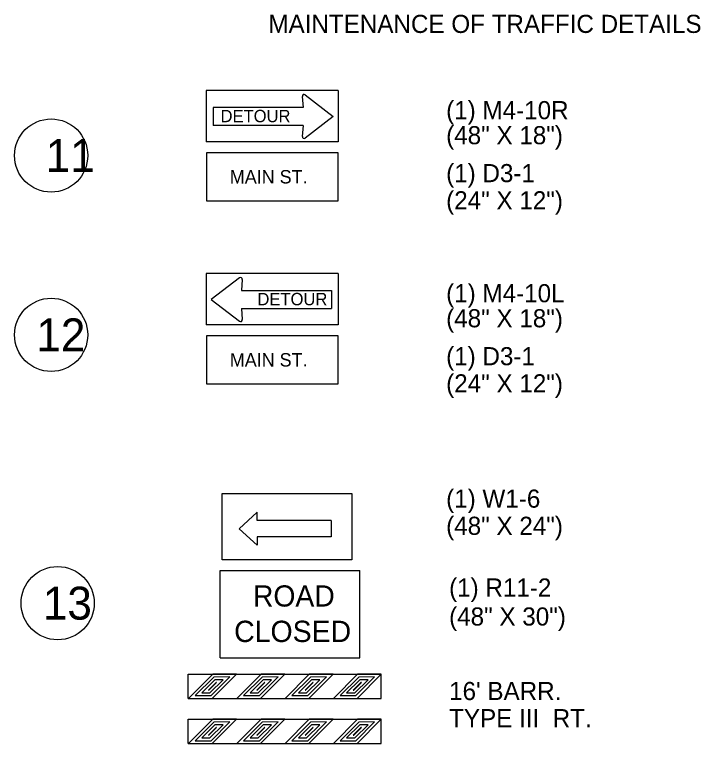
# Model space of a CAD drawing. Extents: x 988392 to 996681, y 1838707 to 1844440.
# Drawn here: x 995431 to 996681, y 1842900 to 1844227 of the extents above; entities that cross this region are included whole.
import ezdxf

# ---------------------------------------------------------------- set-up
doc = ezdxf.new("R2010")
doc.units = 0
for name, color, linetype in [('1', 7, 'Continuous'), ('3', 7, 'Continuous'), ('8', 7, 'Continuous'), ('G-ANNO-TEXT', 7, 'Continuous'), ('Level 8', 7, 'Continuous')]:
    doc.layers.add(name, color=color, linetype=linetype)

msp = doc.modelspace()

# ---------------------------------------------------------------- linework, layer by layer
at = {"layer": '1'}
for p, q in [((996020.9, 1844088.9), (995780.4, 1844088.9)), ((995780.4, 1844088.9), (995780.4, 1843995.4)), ((996020.9, 1844088.9), (996020.9, 1843995.4)), ((995955.4, 1844078), (995957, 1844057.9)), ((995960.7, 1844080.9), (996011.9, 1844041.4)), ((995957, 1844057.9), (995793, 1844057.9)), ((995793, 1844057.9), (995793, 1844024.9)), ((996011.9, 1844041.4), (995960.7, 1844001.9)), ((995957, 1844024.9), (995793, 1844024.9)), ((995957, 1844024.9), (995955.4, 1844004.8)), ((996020.9, 1843995.4), (995780.4, 1843995.4)), ((996020.9, 1843755.4), (995780.4, 1843755.4)), ((995780.4, 1843755.4), (995780.4, 1843662)), ((996020.9, 1843755.4), (996020.9, 1843662)), ((995840.7, 1843747.4), (995789.4, 1843708)), ((995845.9, 1843744.6), (995844.3, 1843724.5)), ((995844.3, 1843724.5), (996008.4, 1843724.5)), ((996008.4, 1843724.5), (996008.4, 1843691.5)), ((995789.4, 1843708), (995840.6, 1843668.5)), ((995844.3, 1843691.5), (996008.4, 1843691.5)), ((995844.3, 1843691.5), (995845.9, 1843671.4)), ((996020.9, 1843662), (995780.4, 1843662))]:
    msp.add_line(p, q, dxfattribs=at)
at = {"layer": '3'}
for p, q in [((995805.4, 1843055.5), (995805.4, 1843214.7)), ((995805.4, 1843214.7), (996060.3, 1843214.7)), ((996060.3, 1843055.5), (996060.3, 1843214.7)), ((995805.4, 1843055.5), (996060.3, 1843055.5)), ((995747.2, 1843025.6), (996099.3, 1843025.6)), ((995747.2, 1842981.4), (995747.2, 1843025.6)), ((996099.3, 1842981.4), (996099.3, 1843025.6)), ((995747.2, 1842981.4), (996099.3, 1842981.4)), ((996099.1, 1842981.5), (996099.3, 1842981.8)), ((995747.2, 1842943.6), (996099.3, 1842943.6)), ((995747.2, 1842899.5), (995747.2, 1842943.6)), ((996099.3, 1842899.5), (996099.3, 1842943.6)), ((996099.3, 1842899.5), (996099.3, 1842943.6)), ((995747.2, 1842899.5), (996099.3, 1842899.5))]:
    msp.add_line(p, q, dxfattribs=at)
for points in [[(995835.3, 1843025.6), (995792.1, 1843025.4), (995748.1, 1842981.5), (995791.3, 1842981.5)], [(995923.3, 1843025.6), (995880.1, 1843025.4), (995836.1, 1842981.5), (995879.3, 1842981.5)], [(996011.3, 1843025.6), (995968.1, 1843025.4), (995924.1, 1842981.5), (995967.3, 1842981.5)], [(996099.3, 1843025.6), (996056.1, 1843025.4), (996012.1, 1842981.5), (996055.3, 1842981.5)], [(995823.2, 1843020.5), (995794.1, 1843020.4), (995760.2, 1842986.5), (995789.2, 1842986.5)], [(995772.2, 1842991.5), (995787.1, 1842991.5), (995811.1, 1843015.5), (995796.2, 1843015.5)], [(995799, 1843010.5), (995798.3, 1843010.5), (995784.3, 1842996.5), (995785, 1842996.5)], [(995911.2, 1843020.5), (995882.1, 1843020.4), (995848.2, 1842986.5), (995877.2, 1842986.5)], [(995860.2, 1842991.5), (995875.1, 1842991.5), (995899.1, 1843015.5), (995884.2, 1843015.5)], [(995887, 1843010.5), (995886.3, 1843010.5), (995872.3, 1842996.5), (995873, 1842996.5)], [(995999.2, 1843020.5), (995970.1, 1843020.4), (995936.2, 1842986.5), (995965.2, 1842986.5)], [(995948.2, 1842991.5), (995963.1, 1842991.5), (995987.1, 1843015.5), (995972.2, 1843015.5)], [(995975, 1843010.5), (995974.3, 1843010.5), (995960.3, 1842996.5), (995961, 1842996.5)], [(996087.2, 1843020.5), (996058.1, 1843020.4), (996024.2, 1842986.5), (996053.2, 1842986.5)], [(996036.2, 1842991.5), (996051.1, 1842991.5), (996075.1, 1843015.5), (996060.2, 1843015.5)], [(996063, 1843010.5), (996062.3, 1843010.5), (996048.3, 1842996.5), (996049, 1842996.5)], [(995835.3, 1842943.6), (995792.1, 1842943.5), (995748.1, 1842899.5), (995791.3, 1842899.5)], [(995823.2, 1842938.6), (995794.1, 1842938.5), (995760.2, 1842904.5), (995789.2, 1842904.5)], [(995772.2, 1842909.5), (995787.1, 1842909.5), (995811.1, 1842933.5), (995796.2, 1842933.5)], [(995923.3, 1842943.6), (995880.1, 1842943.5), (995836.1, 1842899.5), (995879.3, 1842899.5)], [(995911.2, 1842938.6), (995882.1, 1842938.5), (995848.2, 1842904.5), (995877.2, 1842904.5)], [(995860.2, 1842909.5), (995875.1, 1842909.5), (995899.1, 1842933.5), (995884.2, 1842933.5)], [(996011.3, 1842943.6), (995968.1, 1842943.5), (995924.1, 1842899.5), (995967.3, 1842899.5)], [(995999.2, 1842938.6), (995970.1, 1842938.5), (995936.2, 1842904.5), (995965.2, 1842904.5)], [(995948.2, 1842909.5), (995963.1, 1842909.5), (995987.1, 1842933.5), (995972.2, 1842933.5)], [(996099.3, 1842943.6), (996056.1, 1842943.5), (996012.1, 1842899.5), (996055.3, 1842899.5)], [(996087.2, 1842938.6), (996058.1, 1842938.5), (996024.2, 1842904.5), (996053.2, 1842904.5)], [(996036.2, 1842909.5), (996051.1, 1842909.5), (996075.1, 1842933.5), (996060.2, 1842933.5)], [(995799, 1842928.5), (995798.3, 1842928.5), (995784.3, 1842914.5), (995785, 1842914.5)], [(995887, 1842928.5), (995886.3, 1842928.5), (995872.3, 1842914.5), (995873, 1842914.5)], [(995975, 1842928.5), (995974.3, 1842928.5), (995960.3, 1842914.5), (995961, 1842914.5)], [(996063, 1842928.5), (996062.3, 1842928.5), (996048.3, 1842914.5), (996049, 1842914.5)]]:
    msp.add_lwpolyline(points, close=True, dxfattribs=at)
for centre, start, end in [((995958.7, 1844078.2), 52.3853, 184.5739), ((995958.7, 1844004.6), 175.4261, 307.6112), ((995842.7, 1843744.8), 355.4261, 127.6147), ((995842.7, 1843671.1), 232.3888, 4.5739)]:
    msp.add_arc(centre, 3.3, start, end, dxfattribs=at)
at = {"layer": 'Level 8'}
for p, q in [((995873.1, 1843320.6), (995840.2, 1843290.6)), ((995873.1, 1843305.6), (995873.1, 1843320.6)), ((996007.8, 1843305.6), (995873.1, 1843305.6)), ((996007.8, 1843305.6), (996007.8, 1843275.6)), ((995840.2, 1843290.6), (995873.1, 1843260.6)), ((996007.8, 1843275.6), (995873.1, 1843275.6)), ((995873.1, 1843275.6), (995873.1, 1843260.6))]:
    msp.add_line(p, q, dxfattribs=at)
for points in [[(996020.7, 1843975.1), (995780.9, 1843975.1), (995780.9, 1843887.9), (996020.7, 1843887.9)], [(996020.7, 1843641.7), (995780.9, 1843641.7), (995780.9, 1843554.5), (996020.7, 1843554.5)], [(995809.6, 1843354.9), (996045.8, 1843354.9), (996045.8, 1843234.1), (995809.6, 1843234.1)]]:
    msp.add_lwpolyline(points, close=True, dxfattribs=at)
for centre in [(995497.6, 1843970.2), (995497.6, 1843970.2), (995497.6, 1843643.6), (995509.5, 1843155)]:
    msp.add_circle(centre, 66.7, dxfattribs=at)

# ---------------------------------------------------------------- texts
at = {"layer": '3'}
for s, height, p in [('DETOUR', 22.56, (995806.4, 1844030.9)), ('DETOUR', 22.56, (995873.6, 1843697.5)), ('ROAD', 38.59, (995865.4, 1843148.8)), ('CLOSED', 38.78, (995831.1, 1843084.2))]:
    msp.add_text(s, height=height, dxfattribs=at).set_placement(p)
at = {"layer": '8'}
for s, p in [('(1) D3-1', (996217.5, 1843921.7)), ('(24" X 12")', (996217.5, 1843872.2)), ('(1) D3-1', (996217.5, 1843588.3)), ('(24" X 12")', (996217.5, 1843538.8)), ('(1) W1-6', (996217.5, 1843328.9)), ('(48" X 24")', (996217.5, 1843279.4)), ("16' BARR.", (996222.9, 1842978.5)), ('TYPE III  RT.', (996222.9, 1842929))]:
    msp.add_text(s, height=33, rotation=360, dxfattribs=at).set_placement(p)
for s, p in [('(1) R11-2', (996222.9, 1843167)), ('(48" X 30")', (996222.9, 1843114.2))]:
    msp.add_text(s, height=33, dxfattribs=at).set_placement(p)
at = {"layer": 'G-ANNO-TEXT'}
msp.add_text('MAINTENANCE OF TRAFFIC DETAILS', height=33, dxfattribs=at).set_placement((995893.5, 1844193.5))
at = {"layer": 'Level 8'}
for s, height, rotation, p in [('(1) M4-10R', 33, 0, (996217.5, 1844036.4)), ('(48" X 18")', 32.999, 0, (996217.5, 1843990.8)), ('MAIN ST.', 24.43, 0.0858, (995823.3, 1843919.2)), ('(1) M4-10L', 33, 0, (996217.5, 1843703)), ('(48" X 18")', 32.999, 0, (996217.5, 1843657.4)), ('MAIN ST.', 24.43, 0.0858, (995823.3, 1843585.8))]:
    msp.add_text(s, height=height, rotation=rotation, dxfattribs=at).set_placement(p)
for s, p in [('11', (995487.7, 1843940.2)), ('12', (995470.7, 1843613.6)), ('13', (995482.6, 1843125))]:
    msp.add_text(s, height=60, dxfattribs=at).set_placement(p)

doc.saveas('drawing.dxf')
